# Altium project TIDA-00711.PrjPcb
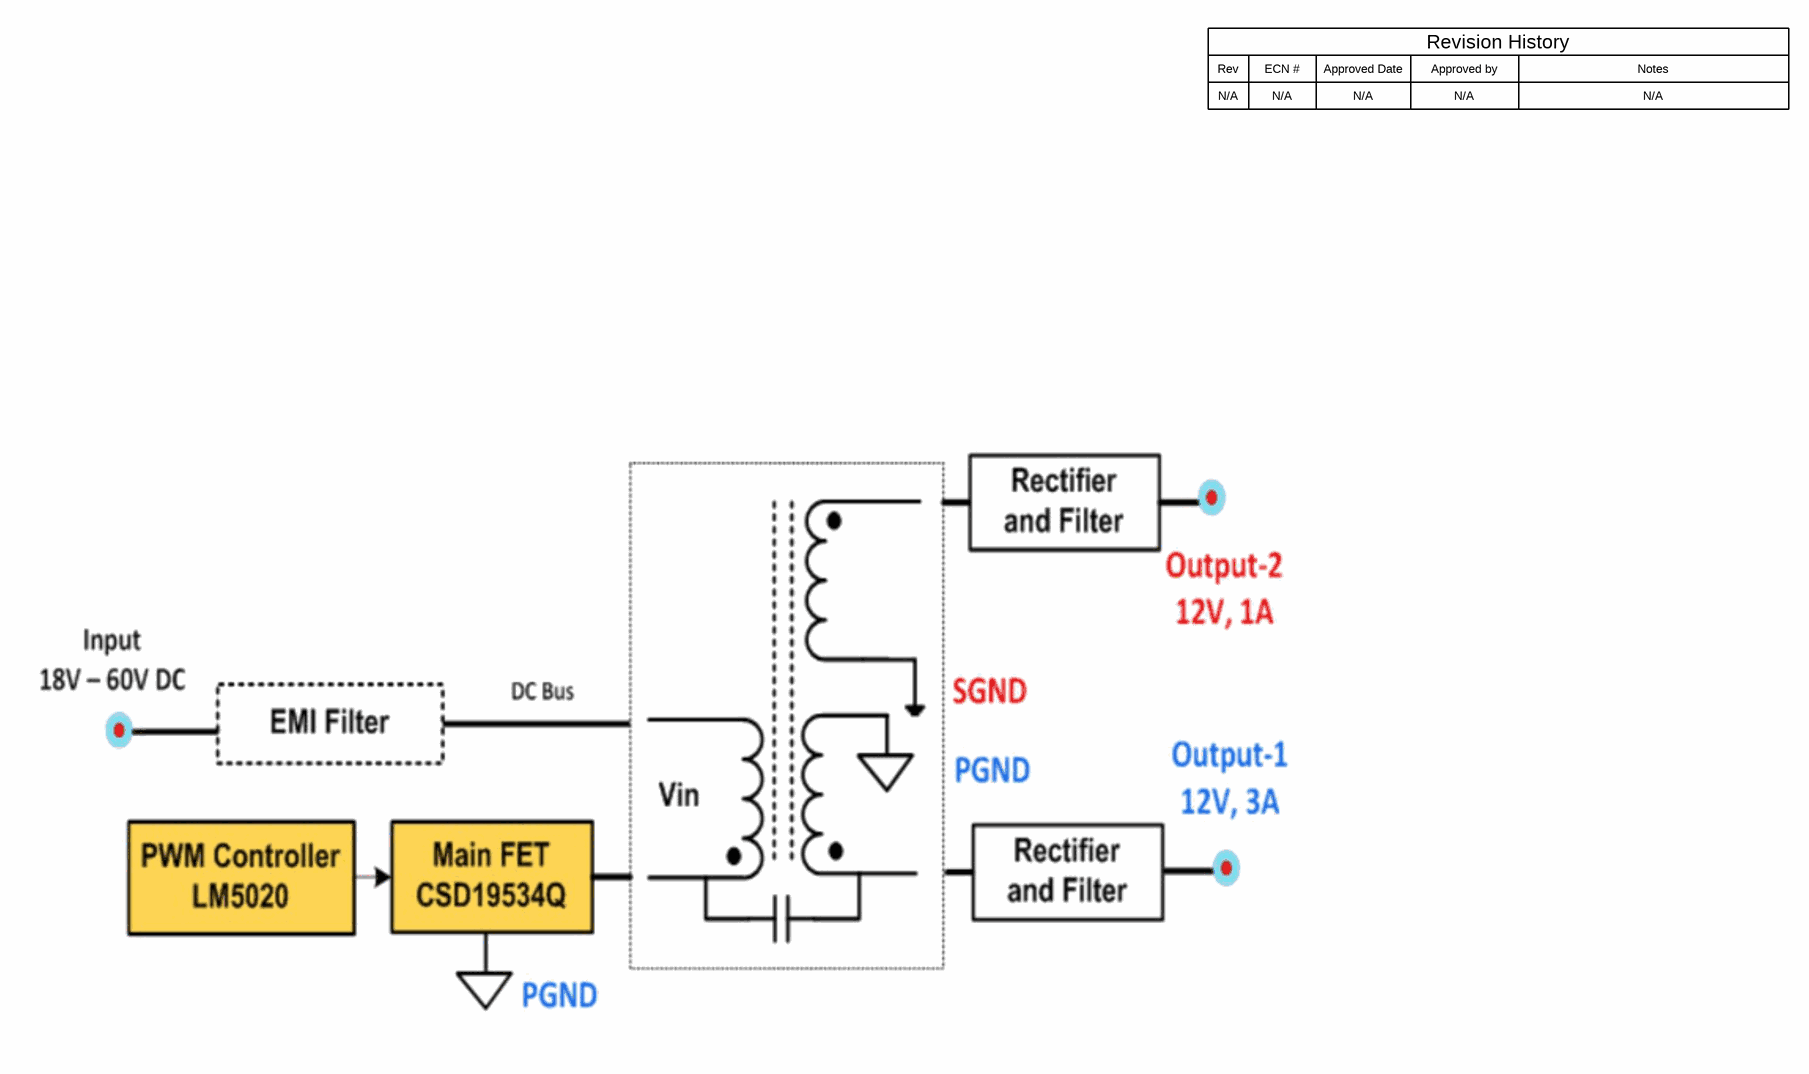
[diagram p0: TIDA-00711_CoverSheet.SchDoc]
CopyrightYear: 2016; EVM_Orderable: N/A; PCB_Layout: Akshay Labhe; PCB_Rev: E1; PRJ_Customer: Public Release; PRJ_Engineer: Aishwarya Nalwaya; PRJ_Number: TIDA-00711; PRJ_Title: Low Cost High Eff. Isolated DC-DC Converter; SCH_Rev: E1; TechSupport: http://www.ti.com/support; TID: TIDA-00711
3 sheets, 58 parts. Net scope: global (net labels, ports and power ports of the same name join across sheets).
Board file: TIDA-00711.PcbDoc
Sheets:
  TIDA-00711_CoverSheet.SchDoc
  TIDA-00711_Sheet1.SchDoc
  TIDA-00711_Hardware.SchDoc

## Sheet TIDA-00711_CoverSheet.SchDoc
size 431 x 279 mm; Date: Not shown in title block; ApprovedBy: Not shown in title block; CheckedBy: Not shown in title block; Author: Not shown in title block; CompanyName: Not shown in title block; DrawnBy: Aishwarya Nalwaya; Engineer: Not shown in title block; Organization: Not shown in title block; Address1: Not shown in title block; Address2: Not shown in title block; Address3: Not shown in title block; Address4: Not shown in title block; DocumentNumber: 1; Revision: Use project parameter SCH_Rev; SheetNumber: 1; SheetTotal: 3; PageSetup: Record=PageOptions¦CenterHorizontal=True¦CenterVertical=True¦PrintScale=1.00¦XCorrection=1.00¦YCorrection=1.00¦PrintKind=0¦BorderSize=5000000¦LeftOffset=0¦BottomOffset=0¦Orientation=2¦PaperLength=1000¦PaperWidth=1000¦Scale=100¦PaperSource=15¦PrintQuality=600¦MediaType=1¦DitherType=10¦PaperKind=Letter¦PrintScaleMode=1

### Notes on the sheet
- Rev
- N/A
- ECN #
- Approved Date
- Approved by
- Revision History
- Notes

## Sheet TIDA-00711_Sheet1.SchDoc
size 431 x 279 mm; Date: Not shown in title block; ApprovedBy: Not shown in title block; CheckedBy: Not shown in title block; Author: Not shown in title block; CompanyName: Not shown in title block; DrawnBy: Aishwarya Nalwaya; Engineer: Not shown in title block; Organization: Not shown in title block; Address1: Not shown in title block; Address2: Not shown in title block; Address3: Not shown in title block; Address4: Not shown in title block; DocumentNumber: 1; Revision: Use project parameter SCH_Rev; SheetNumber: 2; SheetTotal: 3; PageSetup: Record=PageOptions¦CenterHorizontal=True¦CenterVertical=True¦PrintScale=1.00¦XCorrection=1.00¦YCorrection=1.00¦PrintKind=0¦BorderSize=5000000¦LeftOffset=0¦BottomOffset=0¦Orientation=2¦PaperLength=1000¦PaperWidth=1000¦Scale=100¦PaperSource=15¦PrintQuality=600¦MediaType=1¦DitherType=10¦PaperKind=Letter¦PrintScaleMode=1
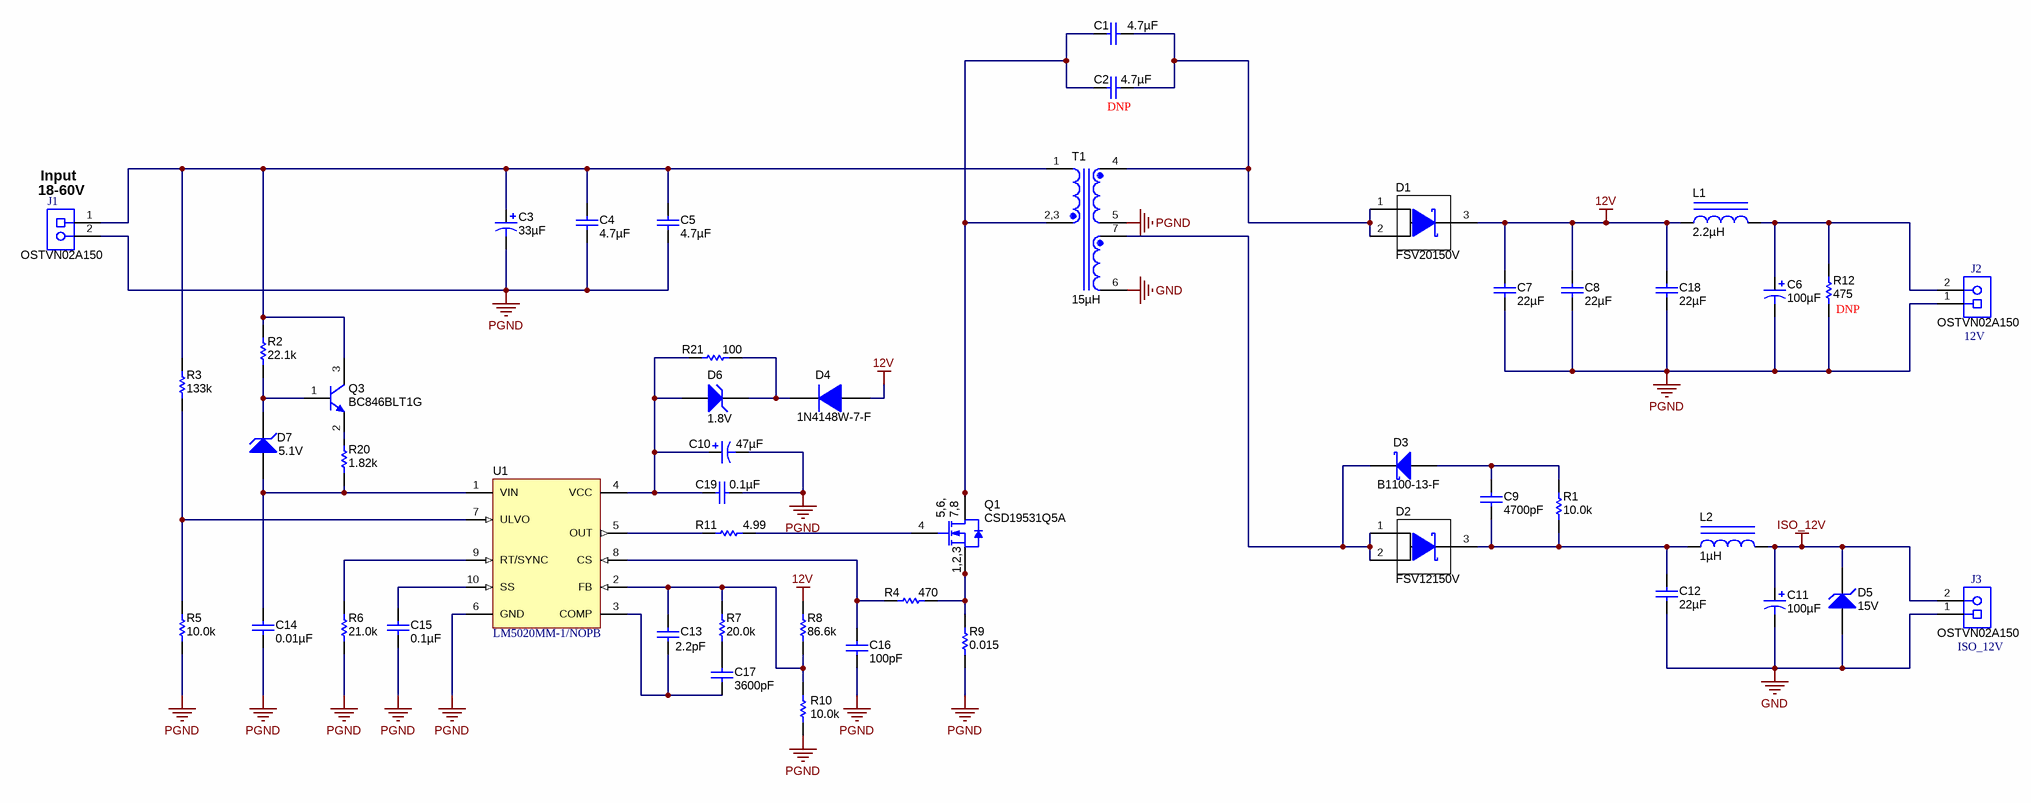
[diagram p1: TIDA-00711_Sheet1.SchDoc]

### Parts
C1  ValueDisplayed: 4.7µF  [1210_270]  (hidden comment: GRM32ER71K475ME14L)
C2  ValueDisplayed: 4.7µF  Installation: DNP  [1210_270]  (hidden comment: GRM32ER71K475ME14L)
C3  ValueDisplayed: 33µF  [KZN_800x1500]  (hidden comment: UPM2A330MPD1TD)
C4  ValueDisplayed: 4.7µF  [1210_270]  (hidden comment: GRM32ER71K475ME14L)
C5  ValueDisplayed: 4.7µF  [1210_270]  (hidden comment: GRM32ER71K475ME14L)
C6  ValueDisplayed: 100µF  [FM_630x1120]  (hidden comment: EEU-FM1E101)
C7  ValueDisplayed: 22µF  [1210_270]  (hidden comment: GRM32ER61E226KE15L)
C8  ValueDisplayed: 22µF  [1210_270]  (hidden comment: GRM32ER61E226KE15L)
C9  ValueDisplayed: 4700pF  [0805_HV]  (hidden comment: GRM21AR72E472KW01D)
C10  ValueDisplayed: 47µF  [ML_500x500]  (hidden comment: ESH476M025AC3AA)
C11  ValueDisplayed: 100µF  [FM_630x1120]  (hidden comment: EEU-FM1E101)
C12  ValueDisplayed: 22µF  [1210_270]  (hidden comment: GRM32ER61E226KE15L)
C13  ValueDisplayed: 2.2pF  [0603]  (hidden comment: 06035A2R2CAT2A)
C14  ValueDisplayed: 0.01µF  [0603]  (hidden comment: 06031C103JAT2A)
C15  ValueDisplayed: 0.1µF  [0603]  (hidden comment: 06033C104JAT2A)
C16  ValueDisplayed: 100pF  [0603]  (hidden comment: GRM1885C2A101JA01D)
C17  ValueDisplayed: 3600pF  [0603]  (hidden comment: GRM1885C1H362JA01D)
C18  ValueDisplayed: 22µF  [1210_270]  (hidden comment: GRM32ER61E226KE15L)
C19  ValueDisplayed: 0.1µF  [0603]  (hidden comment: 06033C104JAT2A)
D1  FSV20150V  [TO-277A]
D2  FSV12150V  [TO-277A]
D3  B1100-13-F  [SMA]
D4  1N4148W-7-F  [SOD-123]
D5  value 15V  [SOD-123]  (hidden comment: MMSZ5245B-TP)
D6  value 1.8V  [SOD-123]  (hidden comment: MMSZ4678-TP)
D7  value 5.1V  [SOD-123]  (hidden comment: MMSZ5231B-7-F)
J1  OSTVN02A150  [On-Shore_OSTVN02A150]
J2  OSTVN02A150  [On-Shore_OSTVN02A150]
J3  OSTVN02A150  [On-Shore_OSTVN02A150]
L1  ValueDisplayed: 2.2µH  [RLB9012]  (hidden comment: RLB0912-2R2ML)
L2  ValueDisplayed: 1µH  [1008]  (hidden comment: CIG22E1R0MNE)
Q1  CSD19531Q5A  [TRANS_NexFET_Q5A]
Q3  BC846BLT1G  [SOT-23]
R1  ValueDisplayed: 10.0k  [2512_084]  (hidden comment: CRM2512-JW-103ELF)
R2  ValueDisplayed: 22.1k  [0603]  (hidden comment: CRCW060322K1FKEA)
R3  ValueDisplayed: 133k  [0603]  (hidden comment: CRCW0603133KFKEA)
R4  ValueDisplayed: 470  [0603]  (hidden comment: RC0603FR-07470RL)
R5  ValueDisplayed: 10.0k  [0603]  (hidden comment: CRCW060310K0FKEA)
R6  ValueDisplayed: 21.0k  [0603]  (hidden comment: RC0603FR-0721KL)
R7  ValueDisplayed: 20.0k  [0603]  (hidden comment: CRCW060320K0FKEA)
R8  ValueDisplayed: 86.6k  [0603]  (hidden comment: RC0603FR-0786K6L)
R9  ValueDisplayed: 0.015  [2512]  (hidden comment: CSRN2512FK15L0)
R10  ValueDisplayed: 10.0k  [0603]  (hidden comment: CRCW060310K0FKEA)
R11  ValueDisplayed: 4.99  [0603]  (hidden comment: CRCW06034R99FKEA)
R12  ValueDisplayed: 475  Installation: DNP  [1206]  (hidden comment: RNCP1206FTD475R)
R20  ValueDisplayed: 1.82k  [0603]  (hidden comment: CRCW06031K82FKEA)
R21  ValueDisplayed: 100  [0603]  (hidden comment: CRCW0603100RFKEA)
T1  ValueDisplayed: 15µH  [WE_750343373]  (hidden comment: 750343373)
U1  LM5020MM-1/NOPB  [MUB10A_N]

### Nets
12V: C7.1 C8.1 C18.1 D1.3(K) D4.2(A) L1.1 R8.2
GND: C11.2(-) C12.2 D5.2(A) J3.1 T1.6
ISO_12V: C11.1(+) D5.1(K) J3.2 L2.2
PGND: C3.2(-) C4.2 C5.2 C6.2(-) C7.2 C8.2 C10.2(-) C14.2 C15.2 C16.2 C18.2 C19.2 J1.2 J2.1 R5.1 R6.1 R9.1 R10.1 R12.1 T1.5 U1.6(GND)
NetC1_1: C1.1 C2.1 Q1.5(D) Q1.6(D) Q1.7(D) Q1.8(D) Q1.9(D) T1.2,3
NetC1_2: C1.2 C2.2 D1.1(A) D1.2(A) T1.4
NetC3_1: C3.1(+) C4.1 C5.1 J1.1 Q3.3(C) R2.2 R3.2 T1.1
NetC6_1: C6.1(+) J2.2 L1.2 R12.2
NetC9_1: C9.1 D3.2(A) R1.1
NetC9_2: C9.2 C12.1 D2.3(K) L2.1 R1.2
NetC10_1: C10.1(+) C19.1 D6.2(A) R21.1 U1.4(VCC)
NetC13_1: C13.1 C17.2 U1.3(COMP)
NetC13_2: C13.2 R7.2 R8.1 R10.2 U1.2(FB)
NetC14_1: C14.1 D7.2(A) R20.1 U1.1(VIN)
NetC15_1: C15.1 U1.10(SS)
NetC16_1: C16.1 R4.1 U1.8(CS)
NetC17_1: C17.1 R7.1
NetD2_1: D2.1(A) D2.2(A) D3.1(K) T1.7
NetD4_1: D4.1(K) D6.1(K) R21.2
NetD7_1: D7.1(K) Q3.1(B) R2.1
NetQ1_1: Q1.1(S) Q1.2(S) Q1.3(S) R4.2 R9.2
NetQ1_4: Q1.4(G) R11.2
NetQ3_2: Q3.2(E) R20.2
NetR3_1: R3.1 R5.2 U1.7(ULVO)
NetR6_2: R6.2 U1.9(RT/SYNC)
NetR11_1: R11.1 U1.5(OUT)

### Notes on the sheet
- (near J1) Input
- (near J1) 18-60V
- (near J2) 12V
- (near J3) ISO_12V

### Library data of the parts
C1 C2 C4 C5 = GRM32ER71K475KE14L: 4.7µF ±20% 80V Ceramic Capacitor X7R 1210 (3225 Metric); Manufacturer: MuRata; Polarized: N; Value: 4.7uF; U/M: EA; Cap_F: 0.0000047; Tolerance_%: 10; Value1: Unknown; VDC_V: 80; TaMin_C: -55; TaMax_C: 125; Cap_Case: 1210; SizeArea_mm2: 8; SizeAreaWB_mm2: 14.7; SizeX_mm: 3.2; SizeY_mm: 2.5; SizeZ_mm: 2.7; AEC Category: Q200
C3 = EKZN101ELL470MH15D: 33µF 100V Aluminum Capacitors Radial, Can 3000 Hrs @ 105°C; Manufacturer: Nichicon; Polarized: Y; U/M: EA; Cap_F: 0.000047; Tolerance_%: 20; Value1: 0.14 ohm; VDC_V: 100; ESR_ohm: 0.14; IRMS_A: 0.78; TaMin_C: -40; TaMax_C: 105; Cap_Case: 8x15mm; AEC Category: Q200; AEC Qualified: N
C6 C11 = EEU-FM1E101: CAP, AL, 100 µF, 25 V, +/- 20%, 0.13 ohm, TH; Manufacturer: Panasonic; Polarized: Y; CompType: Capacitor; Value: 100uF; U/M: EA; Cap_F: 0.0001; Tolerance_%: 20; VDC_V: 25; Value2: 25V; ESR_ohm: 0.13; IRMS_A: 0.455; TaMin_C: -40; TaMax_C: 105; Cap_Case: 6.3x11.2; AEC Category: Q200; AEC Qualified: N
C7 C8 C12 C18 = GRM32ER61E226KE15L: CAP, CERM, 22 µF, 25 V, +/- 10%, X5R, 1210; Manufacturer: MuRata; Polarized: N; CompType: Capacitor; Value: 22uF; U/M: EA; Cap_F: 0.000022; Tolerance_%: 10; ESR_ohm: 0.002; Value1: 0.002 ohm; VDC_V: 25; Value2: 25V; IRMS_A: 3.67; TaMin_C: -55; TaMax_C: 85; Cap_Case: 1210; SizeArea_mm2: 8; SizeAreaWB_mm2: 14.7; SizeX_mm: 3.2; SizeY_mm: 2.5; SizeZ_mm: 2.7; AEC Category: Q200
C9 = GRM21AR72E472KW01D: CAP, CERM, 4700 pF, 250 V, +/- 10%, X7R, 0805; Manufacturer: MuRata; Polarized: N; CompType: Capacitor; Value: 4700pF; U/M: EA; Cap_F: 0.0000000047; Tolerance_%: 10; Value1: Unknown; VDC_V: 250; Value2: 250V; TaMin_C: -55; TaMax_C: 125; Cap_Case: 0805; SizeArea_mm2: 2.5; SizeAreaWB_mm2: 6.75; SizeX_mm: 2; SizeY_mm: 1.25; SizeZ_mm: 1.45; AEC Category: Q200
C10 = 25ML22MEFC5X5: 47µF 25V Aluminum Capacitors Radial, Can 2000 Hrs @ 105°C; Manufacturer: Kemet; Polarized: Y; U/M: EA; Cap_F: 0.000022; Tolerance_%: 20; Value1: Unknown; VDC_V: 25; IRMS_A: 0.042; TaMin_C: -40; TaMax_C: 105; Cap_Case: 5x5; AEC Category: Q200
C13 = 06035A2R2CAT2A: CAP, CERM, 2.2 pF, 50 V, +/- 11%, C0G/NP0, 0603; Manufacturer: AVX; Polarized: N; CompType: Capacitor; Value: 2.2pF; U/M: EA; Cap_F: 0.0000000000022; Tolerance_%: 11; ESR_ohm: 1.033; Value1: 1.033 ohm; VDC_V: 50; Value2: 50V; TaMin_C: -55; TaMax_C: 125; SizeArea_mm2: 1.28; SizeAreaWB_mm2: 4.68; SizeX_mm: 1.6; SizeY_mm: 0.8; SizeZ_mm: 1; AEC Category: Q200
C14 = 06031C103JAT2A: CAP, CERM, 0.01 µF, 100 V, +/- 5%, X7R, 0603; Manufacturer: AVX; Polarized: N; CompType: Capacitor; Value: 0.01uF; U/M: EA; Cap_F: 0.00000001; Tolerance_%: 5; ESR_ohm: 0.098; Value1: 0.098 ohm; VDC_V: 100; Value2: 100V; TaMin_C: -55; TaMax_C: 125; SizeArea_mm2: 1.28; SizeAreaWB_mm2: 4.68; SizeX_mm: 1.6; SizeY_mm: 0.8; SizeZ_mm: 1; AEC Category: Q200
C15 C19 = 06033C104JAT2A: CAP, CERM, 0.1 µF, 25 V, +/- 5%, X7R, 0603; Manufacturer: AVX; Polarized: N; CompType: Capacitor; Value: 0.1uF; U/M: EA; Cap_F: 0.0000001; Tolerance_%: 5; ESR_ohm: 0.05; Value1: 0.05 ohm; VDC_V: 25; Value2: 25V; TaMin_C: -55; TaMax_C: 125; SizeArea_mm2: 1.28; SizeAreaWB_mm2: 4.68; SizeX_mm: 1.6; SizeY_mm: 0.8; SizeZ_mm: 1; AEC Category: Q200
C16 = GRM1885C2A101JA01D: CAP, CERM, 100 pF, 100 V, +/- 5%, C0G/NP0, 0603; Manufacturer: MuRata; Polarized: N; CompType: Capacitor; Value: 100pF; U/M: EA; Cap_F: 0.0000000001; Tolerance_%: 5; Value1: Unknown; VDC_V: 100; Value2: 100V; TaMin_C: -55; TaMax_C: 125; SizeArea_mm2: 1.28; SizeAreaWB_mm2: 4.68; SizeX_mm: 1.6; SizeY_mm: 0.8; SizeZ_mm: 1; AEC Category: Q200
C17 = GRM1885C1H362JA01D: CAP, CERM, 3600 pF, 50 V, +/- 5%, C0G/NP0, 0603; Manufacturer: MuRata; Polarized: N; CompType: Capacitor; Value: 3600pF; U/M: EA; Cap_F: 0.0000000036; Tolerance_%: 5; Value1: Unknown; VDC_V: 50; Value2: 50V; TaMin_C: -55; TaMax_C: 125; SizeArea_mm2: 1.28; SizeAreaWB_mm2: 4.68; SizeX_mm: 1.6; SizeY_mm: 0.8; SizeZ_mm: 1; AEC Category: Q200
D1 = FSV12100V: Diode Schottky 150V 20A Surface Mount TO-277-3; Manufacturer: Fairchild Semiconductor; U/M: EA; Vf_V: 0.67; Value1: 12A; Value2: 0.67V; Io_A: 12; Vr_V: 100; TJmax_C: 150; SizeAreaWB_mm2: 56.1; SizeArea_mm2: 29.9; SizeX_mm: 4.6; SizeY_mm: 6.5; SizeZ_mm: 1.2; AEC Category: Q101; AEC Qualified: Y
D2 = FSV12100V: Diode Schottky 150V 12A Surface Mount TO-277-3; Manufacturer: Fairchild Semiconductor; U/M: EA; Vf_V: 0.67; Value2: 0.67V; Io_A: 12; Vr_V: 100; TJmax_C: 150; SizeAreaWB_mm2: 56.1; SizeArea_mm2: 29.9; SizeX_mm: 4.6; SizeY_mm: 6.5; SizeZ_mm: 1.2; AEC Category: Q101; AEC Qualified: Y
D3 = B1100-13-F: Diode, Schottky, 100 V, 1 A, SMA; Manufacturer: Diodes Inc.; U/M: EA; Vf_V: 0.79; Value: 100V; Value1: 1A; Value2: 0.79V; Io_A: 1; Vr_V: 100; TJmax_C: 150; RJC_CperW: 25; SizeAreaWB_mm2: 37.3428; SizeArea_mm2: 16.3228; SizeX_mm: 5.59; SizeY_mm: 2.92; SizeZ_mm: 2.87; AEC Category: Q101
D4 = 1N4148W-7-F: Diode, Ultrafast, 100 V, 0.15 A, SOD-123; Manufacturer: Diodes Inc.; U/M: EA; Vf_V: 1.25; Value: 100V; Value1: 0.15A; Value2: 1.25V; Io_A: 0.15; Vr_V: 100; TJmax_C: 150; SizeAreaWB_mm2: 13.095; SizeArea_mm2: 6.545; SizeX_mm: 3.85; SizeY_mm: 1.7; SizeZ_mm: 1.35; AEC Category: Q101
D5 = BZT52B16-HE3-08: Zener Diode 15V 500mW ±5% Surface Mount SOD-123; Manufacturer: Micro Commercial Co; SymbolCreator: a0412235; U/M: EA; Power_W: 0.41; Vz_V: 16; Value1: 0.41W; RJA_CperW: 300; SizeAreaWB_mm2: 13.095; SizeArea_mm2: 6.545; SizeX_mm: 3.85; SizeY_mm: 1.7; SizeZ_mm: 1.35; AEC Category: Q101; AEC Qualified: Y
D6 = BZT52B9V1-HE3-08: Zener Diode 1.8V 500mW ±5% Surface Mount SOD-123; Manufacturer: Micro Commercial Co; SymbolCreator: a0412235; U/M: EA; Power_W: 0.41; Vz_V: 9.1; Value1: 0.41W; RJA_CperW: 300; SizeAreaWB_mm2: 13.095; SizeArea_mm2: 6.545; SizeX_mm: 3.85; SizeY_mm: 1.7; SizeZ_mm: 1.35; AEC Category: Q101; AEC Qualified: Y
D7 = BZT52C5V1-G3-08: Zener Diode 5.1V 500mW ±5% Surface Mount SOD-123; Manufacturer: Diodes Incorporated; SymbolCreator: a0412235; U/M: EA; Power_W: 0.5; Vz_V: 5.1; Value1: 0.5W; RJA_CperW: 300; SizeAreaWB_mm2: 13.095; SizeArea_mm2: 6.545; SizeX_mm: 3.85; SizeY_mm: 1.7; SizeZ_mm: 1.35; AEC Category: Q101
J1-J3 = OSTVN02A150: Terminal Block, 2.54mm, 2x1, Brass, TH; Manufacturer: On-Shore Technology; SymbolCreator: a0412235
L1 = DFE252012P-2R2M=P2: Inductor, Shielded, 2.2 µH, 2.6 A, 0.07 ohm, SMD; Manufacturer: MuRata Toko; Value: 2.2uH; Ind_H: 2.2E-6; Imax_A: 2.6; Irms: 2.6A @ 40C rise; Isat: 3.3A @ 30% inductance drop; DCR_ohm: 0.07; Value2: 2.6A; AEC Category: Q200
L2 = CIG22E1R0MNE: Inductor, Multilayer, 1 µH, 2.2 A, 0.048 ohm, SMD; Manufacturer: Samsung; Value: 1uH; Ind_H: 1.0E-6; Imax_A: 2.2; Irms: 2.9A @ 40C rise; Isat: 2.2A @ 30% inductance drop; DCR_ohm: 0.048; Value2: 2.2A; AEC Category: Q200
Q1 = CSD19531Q5A: MOSFET, N-CH, 100 V, 16 A, SON 5x6mm; Manufacturer: Texas Instruments; Alternate Manufacturer: None; U/M: EA; ChType: N; Value: 100V; VdsMax_V: 100; Value1: ? ohm; Value2: 36 nC; QgTyp_nC: 36; Vgs_V: 20; IdsMax_A: 16; SizeAreaWB_mm2: 55.2; SizeArea_mm2: 29.4; SizeX_mm: 6; SizeY_mm: 4.9; SizeZ_mm: 1; AEC Category: Q101
Q3 = BC846BLT1G, ON Semiconductor: Transistor, NPN, 65 V, 0.1 A, SOT-23; CompType: BJT; PNP: 0; NPN: 1; Vceo_V: 65; Vcesat1_V: 0.7; Value: 65 V; IcRated_A: 0.1; Value1: 0.1 A; HfeMax: 450; TaMin_C: -55; TaMax_C: 150; U/M: EA; AEC Category: Q101
R1 = HVCB2512FDD10K0: RES SMD 10K OHM 5% 2W 2512; Manufacturer: Bourns Inc; CompType: Resistor; Value: 10.0k; Res_ohm: 10000; Value_Code: 10k0; Tolerance_%: 1; Value1: 1%; Power_W: 2; VDC_V: 2500; TempCo: 100 ppm/C; EIA_Code: E96; U/M: EA; AEC Category: Q200
R2 = CRCW060322K1FKEA: RES, 22.1 k, 1%, 0.1 W, 0603; Manufacturer: Vishay-Dale; CompType: Resistor; Value: 22.1k; Res_ohm: 22100; Value_Code: 22k1; Tolerance_%: 1; Power_W: 0.1; Value2: 0.1W; VDC_V: 75; TempCo: 100 ppm/C; SizeArea_mm2: 1.28; SizeX_mm: 1.6; SizeY_mm: 0.8; EIA_Code: E96; U/M: EA; AEC Category: Q200
R3 = CRCW0603133KFKEA: RES, 133 k, 1%, 0.1 W, 0603; Manufacturer: Vishay-Dale; CompType: Resistor; Value: 133k; Res_ohm: 133000; Tolerance_%: 1; Power_W: 0.1; Value2: 0.1W; VDC_V: 75; TempCo: 100 ppm/C; SizeArea_mm2: 1.28; SizeX_mm: 1.6; SizeY_mm: 0.8; EIA_Code: E96; U/M: EA; AEC Category: Q200
R4 = RC0603FR-07470RL: RES, 470, 1%, 0.1 W, 0603; Manufacturer: Yageo America; CompType: Resistor; Value: 470; Value_Code: 470R; Tolerance_%: 1; Power_W: 0.1; Value2: 0.1W; VDC_V: 150; TempCo: 200 ppm/C; SizeArea_mm2: 1.28; SizeX_mm: 1.6; SizeY_mm: 0.8; U/M: EA; AEC Category: Q200
R5 R10 = CRCW060310K0FKEA: RES, 10.0 k, 1%, 0.1 W, 0603; Manufacturer: Vishay-Dale; CompType: Resistor; Value: 10.0k; Res_ohm: 10000; Value_Code: 10k0; Tolerance_%: 1; Power_W: 0.1; Value2: 0.1W; VDC_V: 75; TempCo: 100 ppm/C; SizeArea_mm2: 1.28; SizeX_mm: 1.6; SizeY_mm: 0.8; EIA_Code: E96; U/M: EA; AEC Category: Q200
R6 = RC0603FR-0721KL: RES, 21.0 k, 1%, 0.1 W, 0603; Manufacturer: Yageo America; CompType: Resistor; Value: 21.0k; Res_ohm: 21000; Value_Code: 21k0; Tolerance_%: 1; Power_W: 0.1; Value2: 0.1W; VDC_V: 150; TempCo: 200 ppm/C; SizeArea_mm2: 1.28; SizeX_mm: 1.6; SizeY_mm: 0.8; EIA_Code: E96; U/M: EA; AEC Category: Q200
R7 = CRCW060320K0FKEA: RES, 20.0 k, 1%, 0.1 W, 0603; Manufacturer: Vishay-Dale; CompType: Resistor; Value: 20.0k; Res_ohm: 20000; Value_Code: 20k0; Tolerance_%: 1; Power_W: 0.1; Value2: 0.1W; VDC_V: 75; TempCo: 100 ppm/C; SizeArea_mm2: 1.28; SizeX_mm: 1.6; SizeY_mm: 0.8; EIA_Code: E96; U/M: EA; AEC Category: Q200
R8 = RC0603FR-0786K6L: RES, 86.6 k, 1%, 0.1 W, 0603; Manufacturer: Yageo America; CompType: Resistor; Value: 86.6k; Res_ohm: 86600; Value_Code: 86k6; Tolerance_%: 1; Power_W: 0.1; Value2: 0.1W; VDC_V: 150; TempCo: 200 ppm/C; SizeArea_mm2: 1.28; SizeX_mm: 1.6; SizeY_mm: 0.8; EIA_Code: E96; U/M: EA; AEC Category: Q200
R9 = CSRN2512FK15L0: RES, 0.015, 1%, 2 W, 2512; Manufacturer: Stackpole Electronics Inc; CompType: Resistor; Value: 0.015; Value_Code: R015; Tolerance_%: 1; Power_W: 2; Value2: 2W; TempCo: 200 ppm/C; SizeArea_mm2: 20.16; SizeX_mm: 6.3; SizeY_mm: 3.2; SizeZ_mm: 0.71; EIA_Code: E96; U/M: EA; AEC Category: Q200
R11 = CRCW06034R99FKEA: RES, 4.99, 1%, 0.1 W, 0603; Manufacturer: Vishay-Dale; CompType: Resistor; Value: 4.99; Value_Code: 4R99; Tolerance_%: 1; Power_W: 0.1; Value2: 0.1W; VDC_V: 75; TempCo: 100 ppm/C; SizeArea_mm2: 1.28; SizeX_mm: 1.6; SizeY_mm: 0.8; EIA_Code: E96; U/M: EA; AEC Category: Q200
R12 = CRCW1206475RFKEA: RES SMD 475 OHM 1% 1/2W 1206; Manufacturer: Stackpole Electronics Inc.; CompType: Resistor; Value: 475; Value_Code: 475R; Tolerance_%: 1; Power_W: 0.25; Value2: 0.25W; VDC_V: 200; TempCo: 100 ppm/C; SizeArea_mm2: 5.12; SizeX_mm: 3.2; SizeY_mm: 1.6; SizeZ_mm: 1.35; EIA_Code: E96; U/M: EA; AEC Category: Q200
R20 = CRCW06031K82FKEA: RES, 1.82 k, 1%, 0.1 W, 0603; Manufacturer: Vishay-Dale; CompType: Resistor; Value: 1.82k; Res_ohm: 1820; Value_Code: 1k82; Tolerance_%: 1; Power_W: 0.1; Value2: 0.1W; VDC_V: 75; TempCo: 100 ppm/C; SizeArea_mm2: 1.28; SizeX_mm: 1.6; SizeY_mm: 0.8; EIA_Code: E96; U/M: EA; AEC Category: Q200
R21 = CRCW0603100RFKEA: RES, 100, 1%, 0.1 W, 0603; Manufacturer: Vishay-Dale; CompType: Resistor; Value: 100; Value_Code: 100R; Tolerance_%: 1; Power_W: 0.1; Value2: 0.1W; VDC_V: 75; TempCo: 100 ppm/C; SizeArea_mm2: 1.28; SizeX_mm: 1.6; SizeY_mm: 0.8; EIA_Code: E96; U/M: EA; AEC Category: Q200
T1 = G154056LF: Transformer, 15µH, TH; Manufacturer: Wurth Electronics; SymbolCreator: Altium; Lp: 15uH; DCR_ohm: 1; LeakageL: 8
U1 = LM5020MM-1/NOPB: 100V Current Mode PWM Controller, 10-pin MSOP, Pb-Free; Manufacturer: Texas Instruments; PackageTopMarking: ZXTT*SBLB; PowerWise: Y; CompType: Switcher

## Sheet TIDA-00711_Hardware.SchDoc
size 431 x 279 mm; Date: Not shown in title block; ApprovedBy: Not shown in title block; CheckedBy: Not shown in title block; Author: Not shown in title block; CompanyName: Not shown in title block; DrawnBy: Aishwarya Nalwaya; Engineer: Not shown in title block; Organization: Not shown in title block; Address1: Not shown in title block; Address2: Not shown in title block; Address3: Not shown in title block; Address4: Not shown in title block; DocumentNumber: 1; Revision: Use project parameter SCH_Rev; SheetNumber: 3; SheetTotal: 3; PageSetup: Record=PageOptions¦CenterHorizontal=True¦CenterVertical=True¦PrintScale=1.00¦XCorrection=1.00¦YCorrection=1.00¦PrintKind=0¦BorderSize=5000000¦LeftOffset=0¦BottomOffset=0¦Orientation=2¦PaperLength=1000¦PaperWidth=1000¦Scale=100¦PaperSource=15¦PrintQuality=600¦MediaType=1¦DitherType=10¦PaperKind=Letter¦PrintScaleMode=1
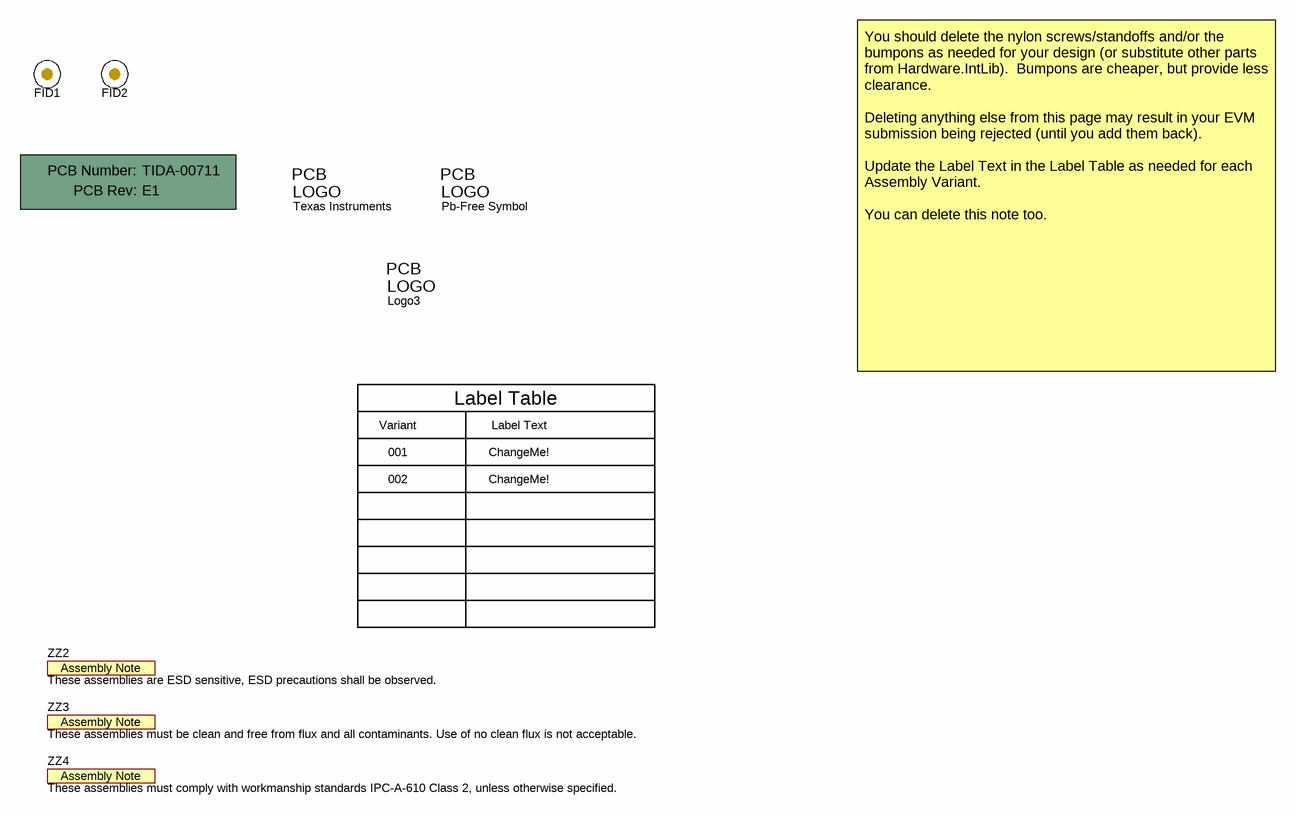
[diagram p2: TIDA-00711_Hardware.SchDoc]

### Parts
!PCB  Printed Circuit Board  (value not drawn)  (mechanical)
FID1  Fiducial  [Fiducial10-20]  (value not drawn)
FID2  Fiducial  [Fiducial10-20]  (value not drawn)
Logo1  Texas Instruments  [TI_Symbol_Overlay_Small]  (no BOM)
Logo2  Pb-Free Symbol  [Pb-Free_Overlay_Small]  (no BOM)
Logo3  ESD Susceptible  [ESD_Overlay_Small]  (value not drawn)  (no BOM)
ZZ2  These assemblies are ESD sensitive, ESD precautions shall be observed.  [AssemblyNote]  (no BOM)
ZZ3  These assemblies must be clean and free from flux and all contaminants. Use of no clean flux is not acceptable.  [AssemblyNote]  (no BOM)
ZZ4  These assemblies must comply with workmanship standards IPC-A-610 Class 2, unless otherwise specified.  [AssemblyNote]  (no BOM)

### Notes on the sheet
- Variant
- Label Table
- Label Text
- You should delete the nylon screws/standoffs and/or the bumpons as needed for your design (or substitute other parts from Hardware.IntLib).  Bumpons are cheaper, but provide less clearance.
  Deleting anything else from this page may result in your EVM submission being rejected (until you add them back).
  Update the Label Text in the Label Table as needed for each Assembly Variant.
  You can delete this note too.
- 001
- 002
- ChangeMe!

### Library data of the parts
!PCB = PCB: Manufacturer: Any; PartNumber: TIDA-00711; SymbolCreator: a0412235
FID1 FID2 = Fiducial: Fiducial mark.  There is nothing to buy or mount.; SymbolCreator: codlsc
Logo1 = TI_Logo: Texas Instrument Corporate Signature; SymbolCreator: codlsc
Logo2 = Pb-Free: SymbolCreator: a0412235
Logo3 = ESD_Susceptible: ESD Susceptible Symbol; SymbolCreator: a0412235
ZZ2-ZZ4 = AssemblyNote: SymbolCreator: codlsc

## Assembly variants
001: not fitted C2 FID1 FID2 R12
